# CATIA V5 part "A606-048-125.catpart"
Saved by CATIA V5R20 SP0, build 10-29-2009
Part number: A606-048-125
Source: Unknown
Property "ARTICLENO": "A606-048-125"
Property "BOMINFO": "A606-048-125"
Property "CODE": "A606-048-125"
Property "HOLES": "2"
Property "L": "125.000"
Property "L1": "25.000"
Property "L2": "75.000"
Property "LINA": "A606-048-125"
Property "NB": "A606-048-125"
Property "NBSYN": "$CODE."
Property "NN": "A606"
Property "NT": "Wear Plates, self-lubricating"
Property "SCREW": "2xM6"
Property "SUPPLIER": "CF"
Property "W": "48.000"
Bounding box of the stored display mesh (mm): x -24 to 24, y -5 to 5, z -62.5 to 62.5
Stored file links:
  C:\Users\Utente\Desktop\3D files A606\A606-048-125.catpart
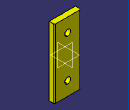
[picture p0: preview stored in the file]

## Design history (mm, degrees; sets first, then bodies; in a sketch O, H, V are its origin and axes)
Body1 "Geometry.1" (main body)
  Solid1 "A606-048-125.catpart": solid without history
